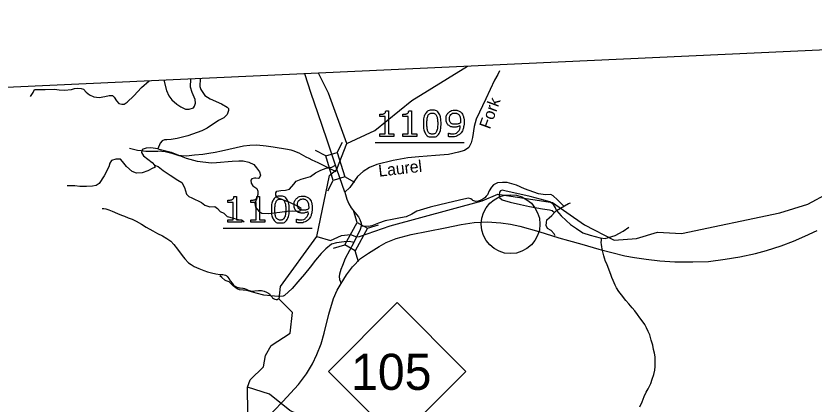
# Model space of a CAD drawing. Extents: x 1190067 to 1192950, y 891516 to 893460.
# Drawn here: x 1190895.6 to 1191031.1, y 893300.9 to 893366.8 of the extents above; entities that cross this region are included whole.
import ezdxf

# ---------------------------------------------------------------- set-up
doc = ezdxf.new("R2010")
doc.units = 0
doc.layers.add('Default', color=7, linetype='Continuous')
doc.layers.add('Prop DSN Text', color=7, linetype='Continuous')

msp = doc.modelspace()

# ---------------------------------------------------------------- linework, layer by layer
at = {"layer": 'Default'}
for p, q in [((1190950.1, 893343.62), (1190951.02, 893345.37)), ((1190956.56, 893345.33), (1190971.68, 893345.33)), ((1190948.2, 893343.04), (1190946.45, 893343.97)), ((1190953.15, 893338.55), (1190951.4, 893339.48)), ((1190948.53, 893337.14), (1190949.46, 893338.89)), ((1190953.52, 893331.73), (1190952.97, 893333.63)), ((1190955.25, 893330.77), (1190957.15, 893331.32)), ((1190930.76, 893330.75), (1190945.88, 893330.75)), ((1190949.51, 893327.39), (1190951.41, 893327.94)), ((1190953.74, 893325.06), (1190953.19, 893326.96)), ((1190948.66, 893306.48), (1190960.31, 893318.14)), ((1190960.31, 893318.14), (1190971.97, 893306.48)), ((1190960.31, 893294.83), (1190948.66, 893306.48)), ((1190971.97, 893306.48), (1190960.31, 893294.83))]:
    msp.add_line(p, q, dxfattribs=at)
for points in [[(1190951.79, 893345.14), (1190956.51, 893347.34), (1190962.78, 893352.44), (1190972.26, 893358.24)], [(1190950.04, 893340.81), (1190949.86, 893341.44), (1190948.41, 893345.71), (1190946.83, 893350.36), (1190945.73, 893353.6), (1190944.61, 893356.97)], [(1190951.79, 893345.14), (1190948.65, 893353.7), (1190946.97, 893357.08)], [(1190977.68, 893357.5), (1190977.4, 893356.85), (1190976.82, 893355.89), (1190975.34, 893352.75), (1190973.72, 893349.26), (1190973.38, 893348.02), (1190973.13, 893346.15), (1190972.89, 893345.24), (1190972.46, 893344.46), (1190971.76, 893343.93), (1190970.74, 893343.65), (1190969.04, 893343.26), (1190966.82, 893343.12), (1190964, 893342.87), (1190962.1, 893342.73), (1190959.66, 893342.27), (1190956.88, 893341.6), (1190955.61, 893341.07), (1190954.55, 893340.37), (1190953.6, 893339.52), (1190952.29, 893337.68), (1190951.41, 893336.87)], [(1190898.72, 893354.3), (1190900.52, 893354.3), (1190902.11, 893354.38), (1190902.93, 893354.25), (1190903.8, 893354.17), (1190904.99, 893354.28), (1190905.52, 893354.46), (1190906.08, 893354.54), (1190906.64, 893354.49), (1190907.06, 893354.38), (1190907.48, 893353.88), (1190908.07, 893353.38), (1190908.83, 893353.06), (1190909.7, 893352.93), (1190910.66, 893353.14), (1190911.42, 893353.3), (1190911.95, 893353.27), (1190912.27, 893353.01), (1190912.66, 893352.37), (1190913.06, 893351.93), (1190913.54, 893351.79), (1190913.96, 893351.82), (1190914.49, 893352.14), (1190915.6, 893353.22), (1190916.92, 893354.62), (1190918.18, 893355.76)], [(1190926.89, 893356.16), (1190926.83, 893354.84), (1190926.96, 893354.31), (1190927.67, 893353.31), (1190928.58, 893352.72), (1190930.48, 893351.85), (1190931.47, 893351.32), (1190931.66, 893351.1), (1190931.69, 893350.73), (1190931.44, 893350.07), (1190930.88, 893349.51), (1190929.98, 893349.07), (1190928.06, 893347.73), (1190927.13, 893347.27), (1190924.76, 893346.46), (1190922.98, 893345.99), (1190921.95, 893345.8), (1190921.21, 893345.74), (1190920.8, 893345.77), (1190920.43, 893345.61), (1190920.05, 893345.21), (1190919.65, 893344.24)], [(1190920.69, 893355.88), (1190921.16, 893354.15), (1190921.53, 893353.22), (1190922.03, 893352.56), (1190922.88, 893351.82), (1190923.59, 893351.34), (1190924.36, 893350.97), (1190924.99, 893350.97), (1190925.71, 893351.18), (1190925.92, 893351.45), (1190926.05, 893351.98), (1190926, 893352.59), (1190925.49, 893353.78), (1190925.23, 893354.68), (1190925.29, 893356.09)], [(1190898.06, 893353.09), (1190898.49, 893353.78), (1190898.72, 893354.3)], [(1190959.73, 893346.35), (1190957.37, 893346.35), (1190957.37, 893346.79), (1190958.28, 893346.79), (1190958.28, 893349.71), (1190957.37, 893349.71), (1190957.37, 893350.1)], [(1190958.39, 893350.71), (1190958.84, 893350.71), (1190958.84, 893346.79), (1190959.73, 893346.79), (1190959.73, 893346.35)], [(1190963.63, 893346.35), (1190961.28, 893346.35), (1190961.28, 893346.79), (1190962.18, 893346.79), (1190962.18, 893349.71), (1190961.28, 893349.71), (1190961.28, 893350.1)], [(1190962.29, 893350.71), (1190962.75, 893350.71), (1190962.75, 893346.79), (1190963.63, 893346.79), (1190963.63, 893346.35)], [(1190953.42, 893329.32), (1190953.91, 893329.36), (1190959.14, 893331.2), (1190974.73, 893335.43), (1190977.39, 893336.52), (1190986.68, 893335.13), (1190992.13, 893331.35), (1190997.16, 893328.72), (1191000.96, 893329.04), (1191004.5, 893330.12), (1191008.57, 893329.87), (1191025.3, 893333.38), (1191030.03, 893334.84), (1191033.58, 893336.78), (1191037.1, 893337.86), (1191041.46, 893342.43), (1191045.9, 893344.35), (1191060.79, 893348.48), (1191064.46, 893347.73), (1191067.53, 893345.7), (1191068.02, 893343.46)], [(1190969.03, 893346.33), (1190969.03, 893346.89), (1190969.06, 893346.89)], [(1190914.89, 893344.34), (1190916.24, 893344.02), (1190916.87, 893343.94), (1190917.61, 893343.85), (1190918.27, 893343.83), (1190919.01, 893343.84), (1190919.67, 893343.86), (1190920.06, 893343.89), (1190920.34, 893343.84), (1190920.9, 893343.79), (1190921.59, 893343.6), (1190922.05, 893343.48), (1190922.88, 893343.21), (1190923.26, 893343.13), (1190923.68, 893343.09), (1190924.52, 893343.06), (1190925.92, 893343.2), (1190927.3, 893343.34), (1190928.35, 893343.48), (1190929.4, 893343.67), (1190930.5, 893343.92), (1190933, 893344.48), (1190934.23, 893344.73), (1190935.28, 893344.84), (1190936.51, 893344.91), (1190938.08, 893344.73), (1190939.24, 893344.59), (1190941.71, 893344.21), (1190942.27, 893344.05), (1190942.76, 893343.9), (1190943.14, 893343.75), (1190943.59, 893343.56), (1190944, 893343.34), (1190944.83, 893342.86), (1190945.31, 893342.64), (1190945.8, 893342.38), (1190946.31, 893342.16), (1190946.83, 893341.9), (1190949.88, 893340.42)], [(1190950.04, 893340.81), (1190951.79, 893345.14)], [(1190919.65, 893344.24), (1190918.5, 893344.4), (1190917.69, 893344.37), (1190917.03, 893344.12), (1190916.91, 893343.62), (1190917.25, 893343.06), (1190918.71, 893341.93), (1190919.12, 893341.47), (1190919.18, 893341.09), (1190918.84, 893340.94), (1190917.97, 893340.5), (1190917, 893340.16), (1190916.03, 893340.09), (1190915.29, 893340.41), (1190914.35, 893341.25), (1190913.67, 893342.09), (1190913.36, 893342.46), (1190912.55, 893342.46), (1190911.8, 893342.25), (1190911.55, 893341.78), (1190911.33, 893341.19), (1190910.58, 893339.66), (1190909.71, 893338.38), (1190909.18, 893338.04), (1190908.57, 893337.88), (1190907.58, 893337.82), (1190906.45, 893337.85), (1190905.61, 893337.97), (1190904.49, 893337.97), (1190904.27, 893337.94)], [(1190919.65, 893344.24), (1190921.95, 893343.65), (1190924.51, 893342.68), (1190926.38, 893342.15), (1190928.78, 893341.87), (1190929.62, 893341.93), (1190932.27, 893342.15), (1190933.42, 893342.21), (1190934.17, 893342.21), (1190935.1, 893342), (1190935.98, 893341.59), (1190936.4, 893341.03), (1190936.93, 893340.34), (1190937.11, 893339.78), (1190936.9, 893339.25), (1190936.77, 893339.19), (1190936.33, 893339.28), (1190936.09, 893339.28), (1190935.65, 893339.16), (1190935.49, 893338.91), (1190935.52, 893338.44), (1190935.8, 893337.94), (1190936.46, 893337.51), (1190936.65, 893337.07), (1190936.68, 893336.51), (1190936.43, 893335.7), (1190936.15, 893334.98), (1190936.24, 893334.36), (1190936.8, 893333.64), (1190937.36, 893333.3), (1190938.39, 893333.27), (1190940.38, 893333.48), (1190941.63, 893333.67), (1190942.6, 893333.7), (1190943.22, 893333.64), (1190943.87, 893333.7), (1190944.03, 893334.14), (1190943.5, 893334.45), (1190942.1, 893335.11), (1190940.01, 893335.95), (1190939.7, 893336.38), (1190939.7, 893336.76), (1190939.89, 893337.04), (1190940.57, 893337.16), (1190941.38, 893337.23), (1190942.01, 893337.41), (1190942.75, 893338.25), (1190943.19, 893338.75), (1190944, 893339.1), (1190945.62, 893339.53), (1190946.46, 893340.16), (1190947.33, 893340.62), (1190948.24, 893340.94), (1190949.23, 893341.15), (1190949.86, 893341.44)], [(1190919.12, 893341.47), (1190919.74, 893341.22), (1190920.58, 893340.59), (1190921.77, 893339.75), (1190923.08, 893338.91), (1190923.73, 893338.54), (1190924.23, 893337.66), (1190924.57, 893336.57), (1190924.95, 893336.13), (1190925.44, 893335.92), (1190927.1, 893335.11), (1190927.63, 893334.67), (1190928.5, 893334.42), (1190929.34, 893334.45), (1190929.78, 893334.14), (1190930.24, 893333.61), (1190930.9, 893333.33), (1190931.43, 893332.77), (1190932.53, 893332.46), (1190933.34, 893332.27), (1190933.97, 893332.11), (1190934.31, 893331.86)], [(1190946.69, 893329.38), (1190948.84, 893339.71), (1190950.04, 893340.81)], [(1190951.41, 893336.87), (1190950.04, 893340.81)], [(1190988.53, 893334.54), (1190987.51, 893335.6), (1190986.82, 893336.25), (1190986.38, 893336.49), (1190985.52, 893336.42), (1190984.32, 893336.63), (1190981.96, 893337.45), (1190980.59, 893338.07), (1190978.98, 893338.51), (1190978.22, 893338.55), (1190977.37, 893338.45), (1190976.65, 893338.14), (1190976.34, 893337.76), (1190975.96, 893337.14), (1190975.65, 893336.42), (1190975.45, 893336.18), (1190975.21, 893335.91), (1190974.69, 893335.6), (1190974.08, 893335.36), (1190973.67, 893335.33), (1190973.15, 893335.5), (1190973.05, 893335.6), (1190972.81, 893335.77), (1190972.43, 893335.84), (1190971.61, 893335.7), (1190968.96, 893335.05), (1190965.91, 893334.33), (1190963.65, 893333.65), (1190962.83, 893333.17), (1190961.83, 893332.69), (1190960.87, 893332.55), (1190959.47, 893332.24), (1190958.27, 893332), (1190957.17, 893331.62), (1190956.01, 893331.18), (1190955.44, 893331.08), (1190954.18, 893331.14)], [(1190951.41, 893336.87), (1190951.79, 893335.71), (1190952.13, 893334.93), (1190952.49, 893334.22), (1190953.15, 893333.45), (1190953.74, 893332.72), (1190954, 893332.27), (1190954.19, 893331.64), (1190954.18, 893331.14), (1190954.03, 893330.55), (1190953.65, 893329.7), (1190953.42, 893329.32)], [(1190987.16, 893329.46), (1190986.99, 893329.81), (1190986.44, 893330.36), (1190985.83, 893330.73), (1190985.62, 893331.21), (1190985.66, 893331.76), (1190985.72, 893332.17), (1190986.1, 893332.52), (1190986.58, 893332.93), (1190987.03, 893333.44), (1190987.37, 893333.75), (1190987.2, 893334.23), (1190986.86, 893334.81), (1190986.24, 893335.22), (1190985.45, 893335.46), (1190982.92, 893336.15), (1190980.62, 893336.66), (1190978.81, 893337.07), (1190978.15, 893337.21), (1190977.88, 893337.14), (1190977.71, 893336.87), (1190977.61, 893336.42), (1190977.71, 893335.98), (1190978.12, 893335.57), (1190979.49, 893335.19), (1190981.24, 893334.81)], [(1190933.93, 893331.77), (1190931.57, 893331.77), (1190931.57, 893332.21), (1190932.48, 893332.21), (1190932.48, 893335.12), (1190931.57, 893335.12), (1190931.57, 893335.52)], [(1190932.59, 893336.13), (1190933.04, 893336.13), (1190933.04, 893332.21), (1190933.93, 893332.21), (1190933.93, 893331.77)], [(1190937.83, 893331.77), (1190935.48, 893331.77), (1190935.48, 893332.21), (1190936.38, 893332.21), (1190936.38, 893335.12), (1190935.48, 893335.12), (1190935.48, 893335.52)], [(1190936.49, 893336.13), (1190936.95, 893336.13), (1190936.95, 893332.21), (1190937.83, 893332.21), (1190937.83, 893331.77)], [(1190987.37, 893333.75), (1190989.42, 893334.95), (1190989.73, 893335.09)], [(1190910.23, 893334.13), (1190910.51, 893334.09), (1190910.86, 893334.05), (1190911.35, 893333.89), (1190911.9, 893333.67), (1190912.84, 893333.26), (1190913.49, 893333), (1190914.01, 893332.81), (1190914.64, 893332.54), (1190915.3, 893332.28), (1190915.99, 893331.98), (1190916.89, 893331.47), (1190917.71, 893330.95), (1190918.82, 893330.33), (1190919.64, 893329.89), (1190920.47, 893329.48), (1190921.2, 893329.04), (1190921.89, 893328.56), (1190922.4, 893328.03), (1190923.01, 893327.2), (1190923.78, 893326.13), (1190924.26, 893325.56), (1190924.9, 893324.91), (1190925.35, 893324.62), (1190925.87, 893324.29), (1190926.66, 893323.92), (1190927.5, 893323.58), (1190928.12, 893323.39), (1190928.81, 893323.19), (1190929.54, 893323.03), (1190930.28, 893322.94), (1190930.73, 893322.9), (1190931.15, 893322.78), (1190931.25, 893322.74), (1190931.36, 893322.7), (1190931.46, 893322.63), (1190931.53, 893322.53), (1190931.77, 893322.17), (1190931.86, 893321.99), (1190932, 893321.78), (1190932.27, 893321.45), (1190932.41, 893321.27), (1190932.54, 893321.1), (1190932.68, 893320.99), (1190932.78, 893320.92), (1190932.89, 893320.84), (1190933.02, 893320.8), (1190933.16, 893320.73), (1190933.3, 893320.69), (1190933.51, 893320.65), (1190933.68, 893320.64), (1190934.1, 893320.6), (1190934.28, 893320.56), (1190934.38, 893320.52), (1190934.69, 893320.41), (1190935, 893320.26), (1190935.21, 893320.18), (1190935.39, 893320.14), (1190935.56, 893320.1), (1190935.74, 893320.1), (1190936.16, 893320.16), (1190936.76, 893320.21), (1190937.04, 893320.2), (1190937.28, 893320.2), (1190937.52, 893320.12), (1190937.73, 893320.08), (1190938.11, 893319.93), (1190938.25, 893319.86), (1190938.35, 893319.78), (1190938.46, 893319.71), (1190938.56, 893319.64), (1190938.77, 893319.42), (1190939.07, 893319.06), (1190939.17, 893318.96), (1190939.31, 893318.85), (1190939.45, 893318.77), (1190939.55, 893318.74), (1190939.76, 893318.69), (1190939.94, 893318.65), (1190940.29, 893318.88)], [(1190981.24, 893334.81), (1190982.78, 893334.44), (1190984.97, 893334.06), (1190986.2, 893333.89), (1190986.65, 893333.75), (1190987.03, 893333.44)], [(1190987.37, 893333.75), (1190988.16, 893332.89), (1190988.98, 893332.07), (1190989.77, 893331.38), (1190990.76, 893330.7), (1190991.82, 893330.01), (1190993.06, 893329.57), (1190994.8, 893329.12), (1190995.62, 893329.05), (1190997.3, 893329.53), (1190998.67, 893330.25), (1190999.67, 893330.94)], [(1190943.23, 893331.75), (1190943.23, 893332.31), (1190943.26, 893332.31)], [(1190950.8, 893321.41), (1190951.73, 893322.84), (1190952.7, 893324.24), (1190954.06, 893325.64), (1190955.42, 893326.53), (1190957.25, 893327.69), (1190958.43, 893328.34), (1190960.13, 893329.01), (1190962.68, 893329.68), (1190968.44, 893330.83), (1190971.18, 893331.41), (1190973.4, 893331.75), (1190975.58, 893331.86), (1190977.93, 893331.68), (1190979.56, 893331.46), (1190981.12, 893331.13)], [(1190981.12, 893331.13), (1190981.14, 893331.12), (1190984.39, 893330.21), (1190987.74, 893329.16), (1190989.41, 893328.69), (1190991.66, 893328.05), (1190994.57, 893327.2), (1190998.97, 893326.11), (1191000.61, 893325.82), (1191002.6, 893325.49), (1191004.89, 893325.22), (1191007.47, 893325.06), (1191010.51, 893325.09), (1191013.2, 893325.15), (1191016.03, 893325.49), (1191018.48, 893325.89), (1191021.18, 893326.49), (1191023.01, 893327), (1191025.52, 893327.76), (1191027.61, 893328.56), (1191029.53, 893329.41), (1191031.63, 893330.39)], [(1190948.99, 893328.66), (1190950.86, 893329.52), (1190952.38, 893329.7), (1190953.42, 893329.32)], [(1190952.93, 893328.37), (1190952.24, 893328.51), (1190951.32, 893328.44), (1190950.01, 893328.3), (1190949.19, 893328.06), (1190948.2, 893327.27), (1190947.41, 893326.48), (1190946.45, 893325.35), (1190945.56, 893324.15), (1190944.6, 893322.99), (1190943.47, 893321.65), (1190942.48, 893320.52), (1190941.18, 893319.35), (1190940.94, 893319.22), (1190940.11, 893319.18), (1190938.88, 893319.32), (1190937.68, 893319.42), (1190936.35, 893319.73), (1190934.77, 893320.21), (1190933.54, 893320.31), (1190933.16, 893320.48), (1190932.44, 893321), (1190931.76, 893321.68), (1190931.28, 893321.82), (1190931.04, 893321.96), (1190930.52, 893322.4), (1190930.2, 893322.68)], [(1190934.9, 893303.82), (1190935.37, 893305.02), (1190937.63, 893307.27), (1190937.96, 893309.16), (1190938.89, 893310.87), (1190942.16, 893312.99), (1190942.55, 893316.48), (1190940.27, 893318.71), (1190940.48, 893320.89), (1190946.69, 893329.38)], [(1190946.69, 893329.38), (1190948.99, 893328.66)], [(1190953.42, 893329.32), (1190952.93, 893328.37), (1190951.51, 893325.61), (1190951.02, 893324.45), (1190950.73, 893323.76), (1190950.53, 893323), (1190950.47, 893322.55), (1190950.52, 893322.08), (1190950.8, 893321.41)], [(1191001.51, 893300.49), (1191001.91, 893301.32), (1191002.25, 893302.19), (1191002.59, 893302.95), (1191002.95, 893303.54), (1191003.4, 893304.43), (1191003.63, 893305.16), (1191003.9, 893305.93), (1191004.05, 893306.66), (1191004.14, 893307.29), (1191004.13, 893308.16), (1191004.12, 893308.93), (1191003.99, 893309.57), (1191003.83, 893310.17), (1191003.72, 893310.94), (1191003.46, 893311.79), (1191003.2, 893312.67), (1191002.94, 893313.27), (1191002.67, 893313.88), (1191002.34, 893314.45), (1191001.9, 893315.05), (1191001.53, 893315.55), (1191001.12, 893316.12), (1191000.65, 893316.73), (1191000.21, 893317.27), (1190999.63, 893317.92), (1190999.12, 893318.49), (1190998.38, 893319.46), (1190997.94, 893320.06), (1190997.53, 893320.63), (1190997.34, 893321.1), (1190996.97, 893321.88), (1190996.78, 893322.41), (1190996.58, 893322.9), (1190996.28, 893323.65), (1190995.89, 893324.71), (1190995.69, 893325.13), (1190995.5, 893325.7), (1190995.4, 893326.08), (1190995.31, 893326.54), (1190995.18, 893327), (1190995.12, 893327.25), (1190995.06, 893327.63), (1190995, 893328.02), (1190994.97, 893328.37), (1190994.98, 893328.72), (1190994.99, 893328.97), (1190994.99, 893329.11)], [(1190929.74, 893289.33), (1190931.32, 893291.1), (1190933.23, 893293.13), (1190937.96, 893298.19), (1190939.36, 893299.8), (1190940.91, 893301.36), (1190943.54, 893304.28), (1190944.89, 893306.09), (1190945.94, 893307.78), (1190946.67, 893309.33), (1190947.4, 893311.14), (1190947.93, 893312.98), (1190948.72, 893316.16), (1190949.5, 893318.83), (1190950.11, 893320.28), (1190950.8, 893321.41)], [(1190925.25, 893290.05), (1190926.33, 893291.36), (1190927.71, 893292.9), (1190928.4, 893293.97), (1190930.01, 893295.05), (1190931.4, 893296.74), (1190934.93, 893299.46), (1190934.9, 893303.82)], [(1190980.7, 893248.45), (1190979.49, 893247.04), (1190979.74, 893245.42), (1190981.5, 893246.08), (1190983.88, 893247.93), (1190988.98, 893247.08), (1190989.71, 893247.64), (1190989.4, 893251.89), (1190988.4, 893253.06), (1190988.57, 893253.63), (1190985.2, 893258.53), (1190981.71, 893269.91), (1190981.34, 893272.51), (1190978.6, 893279.28), (1190976.36, 893282.43), (1190970.81, 893288), (1190966.35, 893289.98), (1190961.81, 893295.36), (1190956.88, 893295.8), (1190952.52, 893297.1), (1190945.98, 893297.97), (1190942.09, 893299.83), (1190938.66, 893302.6), (1190934.9, 893303.82)], [(1190980.7, 893248.45), (1190979.49, 893247.04), (1190979.74, 893245.42), (1190981.5, 893246.08), (1190983.88, 893247.93), (1190988.98, 893247.08), (1190989.71, 893247.64), (1190989.4, 893251.89), (1190988.4, 893253.06), (1190988.57, 893253.63), (1190985.2, 893258.53), (1190981.71, 893269.91), (1190981.34, 893272.51), (1190978.6, 893279.28), (1190976.36, 893282.43), (1190970.81, 893288), (1190966.35, 893289.98), (1190961.81, 893295.36), (1190956.88, 893295.8), (1190952.52, 893297.1), (1190945.98, 893297.97), (1190942.09, 893299.83), (1190938.66, 893302.6), (1190934.9, 893303.82)]]:
    msp.add_lwpolyline(points, dxfattribs=at)
for points in [[(1190949.46, 893338.89), (1190948.19, 893343.03), (1190950.13, 893343.63), (1190951.4, 893339.48)], [(1190951.41, 893327.94), (1190953.51, 893331.74), (1190955.28, 893330.76), (1190953.19, 893326.96)]]:
    msp.add_lwpolyline(points, close=True, dxfattribs=at)
for points in [[(1190957.37, 893350.1), (1190957.56, 893350.1), (1190957.77, 893350.13), (1190957.98, 893350.16), (1190958.09, 893350.22), (1190958.22, 893350.3), (1190958.3, 893350.41), (1190958.38, 893350.52), (1190958.39, 893350.71)], [(1190961.28, 893350.1), (1190961.46, 893350.1), (1190961.67, 893350.13), (1190961.88, 893350.16), (1190961.99, 893350.22), (1190962.13, 893350.3), (1190962.2, 893350.41), (1190962.28, 893350.52), (1190962.29, 893350.71)], [(1190967.78, 893348.52), (1190967.78, 893347.35), (1190967.41, 893346.8), (1190967.05, 893346.25), (1190966.28, 893346.25), (1190965.49, 893346.25), (1190965.13, 893346.81), (1190964.77, 893347.37), (1190964.77, 893348.52), (1190964.77, 893349.68), (1190965.14, 893350.23), (1190965.5, 893350.79), (1190966.28, 893350.79), (1190967.06, 893350.79), (1190967.42, 893350.23), (1190967.78, 893349.66), (1190967.78, 893348.52)], [(1190967.01, 893347.2), (1190967.11, 893347.43), (1190967.15, 893347.75), (1190967.19, 893348.07), (1190967.19, 893348.52), (1190967.19, 893348.97), (1190967.15, 893349.3), (1190967.11, 893349.62), (1190967.01, 893349.85), (1190966.91, 893350.08), (1190966.73, 893350.19), (1190966.55, 893350.31), (1190966.28, 893350.31), (1190966, 893350.31), (1190965.82, 893350.19), (1190965.64, 893350.08), (1190965.54, 893349.85), (1190965.44, 893349.63), (1190965.4, 893349.28), (1190965.36, 893348.93), (1190965.36, 893348.52), (1190965.36, 893348.06), (1190965.4, 893347.76), (1190965.43, 893347.45), (1190965.53, 893347.21), (1190965.63, 893346.98), (1190965.81, 893346.86), (1190965.98, 893346.74), (1190966.28, 893346.74), (1190966.55, 893346.74), (1190966.73, 893346.85), (1190966.91, 893346.97), (1190967.01, 893347.2)], [(1190969.06, 893346.89), (1190969.14, 893346.85), (1190969.3, 893346.81), (1190969.45, 893346.77), (1190969.64, 893346.77), (1190970.29, 893346.77), (1190970.65, 893347.15), (1190971.02, 893347.54), (1190971.08, 893348.22), (1190970.81, 893348.06), (1190970.57, 893347.99), (1190970.33, 893347.92), (1190970.04, 893347.92), (1190969.78, 893347.92), (1190969.56, 893347.97), (1190969.34, 893348.02), (1190969.12, 893348.17), (1190968.87, 893348.35), (1190968.74, 893348.63), (1190968.61, 893348.9), (1190968.61, 893349.29), (1190968.61, 893349.95), (1190969.04, 893350.37), (1190969.48, 893350.79), (1190970.11, 893350.79), (1190970.43, 893350.79), (1190970.7, 893350.69), (1190970.97, 893350.59), (1190971.17, 893350.4), (1190971.42, 893350.15), (1190971.55, 893349.77), (1190971.68, 893349.39), (1190971.68, 893348.79)], [(1190971.09, 893348.91), (1190971.09, 893349.37), (1190971, 893349.64), (1190970.9, 893349.92), (1190970.74, 893350.07), (1190970.6, 893350.2), (1190970.45, 893350.26), (1190970.29, 893350.31), (1190970.11, 893350.31), (1190969.69, 893350.31), (1190969.44, 893350.05), (1190969.2, 893349.79), (1190969.2, 893349.31), (1190969.2, 893349.03), (1190969.28, 893348.86), (1190969.36, 893348.68), (1190969.54, 893348.55), (1190969.67, 893348.46), (1190969.83, 893348.43), (1190969.99, 893348.4), (1190970.18, 893348.4), (1190970.41, 893348.4), (1190970.64, 893348.46), (1190970.88, 893348.52), (1190971.08, 893348.64), (1190971.08, 893348.7), (1190971.09, 893348.76), (1190971.09, 893348.82), (1190971.09, 893348.91)], [(1190971.68, 893348.79), (1190971.68, 893348.22), (1190971.55, 893347.75), (1190971.42, 893347.28), (1190971.16, 893346.96), (1190970.9, 893346.62), (1190970.49, 893346.44), (1190970.09, 893346.26), (1190969.55, 893346.26), (1190969.4, 893346.26), (1190969.27, 893346.28), (1190969.13, 893346.29), (1190969.03, 893346.33)], [(1190931.57, 893335.52), (1190931.76, 893335.52), (1190931.97, 893335.55), (1190932.18, 893335.58), (1190932.29, 893335.64), (1190932.42, 893335.72), (1190932.5, 893335.83), (1190932.58, 893335.94), (1190932.59, 893336.13)], [(1190935.48, 893335.52), (1190935.66, 893335.52), (1190935.87, 893335.55), (1190936.08, 893335.58), (1190936.19, 893335.64), (1190936.33, 893335.72), (1190936.4, 893335.83), (1190936.48, 893335.94), (1190936.49, 893336.13)], [(1190941.98, 893333.94), (1190941.98, 893332.77), (1190941.61, 893332.22), (1190941.25, 893331.67), (1190940.48, 893331.67), (1190939.69, 893331.67), (1190939.33, 893332.23), (1190938.97, 893332.78), (1190938.97, 893333.94), (1190938.97, 893335.1), (1190939.34, 893335.65), (1190939.7, 893336.21), (1190940.48, 893336.21), (1190941.26, 893336.21), (1190941.62, 893335.64), (1190941.98, 893335.08), (1190941.98, 893333.94)], [(1190941.21, 893332.62), (1190941.31, 893332.85), (1190941.35, 893333.17), (1190941.39, 893333.49), (1190941.39, 893333.94), (1190941.39, 893334.39), (1190941.35, 893334.72), (1190941.31, 893335.04), (1190941.21, 893335.27), (1190941.11, 893335.5), (1190940.93, 893335.61), (1190940.75, 893335.72), (1190940.48, 893335.72), (1190940.2, 893335.72), (1190940.02, 893335.61), (1190939.84, 893335.5), (1190939.74, 893335.27), (1190939.64, 893335.05), (1190939.6, 893334.7), (1190939.56, 893334.35), (1190939.56, 893333.94), (1190939.56, 893333.48), (1190939.6, 893333.17), (1190939.63, 893332.87), (1190939.73, 893332.62), (1190939.83, 893332.4), (1190940.01, 893332.28), (1190940.18, 893332.16), (1190940.48, 893332.16), (1190940.75, 893332.16), (1190940.93, 893332.27), (1190941.11, 893332.38), (1190941.21, 893332.62)], [(1190943.26, 893332.31), (1190943.34, 893332.26), (1190943.5, 893332.22), (1190943.65, 893332.18), (1190943.84, 893332.18), (1190944.49, 893332.18), (1190944.85, 893332.57), (1190945.22, 893332.96), (1190945.28, 893333.64), (1190945.01, 893333.48), (1190944.77, 893333.41), (1190944.53, 893333.33), (1190944.24, 893333.33), (1190943.98, 893333.33), (1190943.76, 893333.39), (1190943.54, 893333.44), (1190943.32, 893333.59), (1190943.07, 893333.77), (1190942.94, 893334.05), (1190942.81, 893334.32), (1190942.81, 893334.7), (1190942.81, 893335.37), (1190943.24, 893335.79), (1190943.68, 893336.21), (1190944.31, 893336.21), (1190944.63, 893336.21), (1190944.9, 893336.11), (1190945.17, 893336.01), (1190945.37, 893335.82), (1190945.62, 893335.57), (1190945.75, 893335.19), (1190945.88, 893334.81), (1190945.88, 893334.2)], [(1190945.29, 893334.33), (1190945.29, 893334.79), (1190945.2, 893335.06), (1190945.1, 893335.33), (1190944.94, 893335.49), (1190944.8, 893335.62), (1190944.65, 893335.67), (1190944.49, 893335.73), (1190944.31, 893335.73), (1190943.89, 893335.73), (1190943.64, 893335.47), (1190943.4, 893335.21), (1190943.4, 893334.73), (1190943.4, 893334.45), (1190943.48, 893334.28), (1190943.56, 893334.1), (1190943.74, 893333.97), (1190943.87, 893333.88), (1190944.03, 893333.85), (1190944.19, 893333.82), (1190944.38, 893333.82), (1190944.61, 893333.82), (1190944.84, 893333.88), (1190945.08, 893333.94), (1190945.28, 893334.06), (1190945.28, 893334.12), (1190945.29, 893334.18), (1190945.29, 893334.24), (1190945.29, 893334.33)], [(1190945.88, 893334.2), (1190945.88, 893333.63), (1190945.75, 893333.17), (1190945.62, 893332.7), (1190945.36, 893332.38), (1190945.1, 893332.04), (1190944.69, 893331.86), (1190944.29, 893331.68), (1190943.75, 893331.68), (1190943.6, 893331.68), (1190943.47, 893331.7), (1190943.33, 893331.71), (1190943.23, 893331.75)]]:
    msp.add_open_spline(points, degree=3, dxfattribs=at)
at = {"layer": 'Prop DSN Text'}
msp.add_lwpolyline([(1191159.03, 893366.78), (1190838.38, 893352.11), (1190851.29, 893069.99), (1191171.94, 893084.66)], dxfattribs=at)
msp.add_lwpolyline([(1191159.03, 893366.78), (1190838.38, 893352.11), (1190851.29, 893069.99), (1191171.94, 893084.66)], dxfattribs=at)
msp.add_lwpolyline([(1191159.03, 893366.78), (1190838.38, 893352.11), (1190851.29, 893069.99), (1191171.94, 893084.66)], dxfattribs=at)
msp.add_circle((1190979.56, 893331.46), 5, dxfattribs=at)
msp.add_circle((1190979.56, 893331.46), 5, dxfattribs=at)

# ---------------------------------------------------------------- texts
at = {"layer": 'Default'}
for s, rotation, p in [('Fork', 69.8353, (1190976.05, 893347.46)), ('Laurel', 6.6656, (1190957.24, 893339.5))]:
    msp.add_text(s, height=2, rotation=rotation, dxfattribs=at).set_placement(p)
msp.add_text('105', height=6.125, dxfattribs=at).set_placement((1190952.48, 893303.34))

doc.saveas('drawing.dxf')
